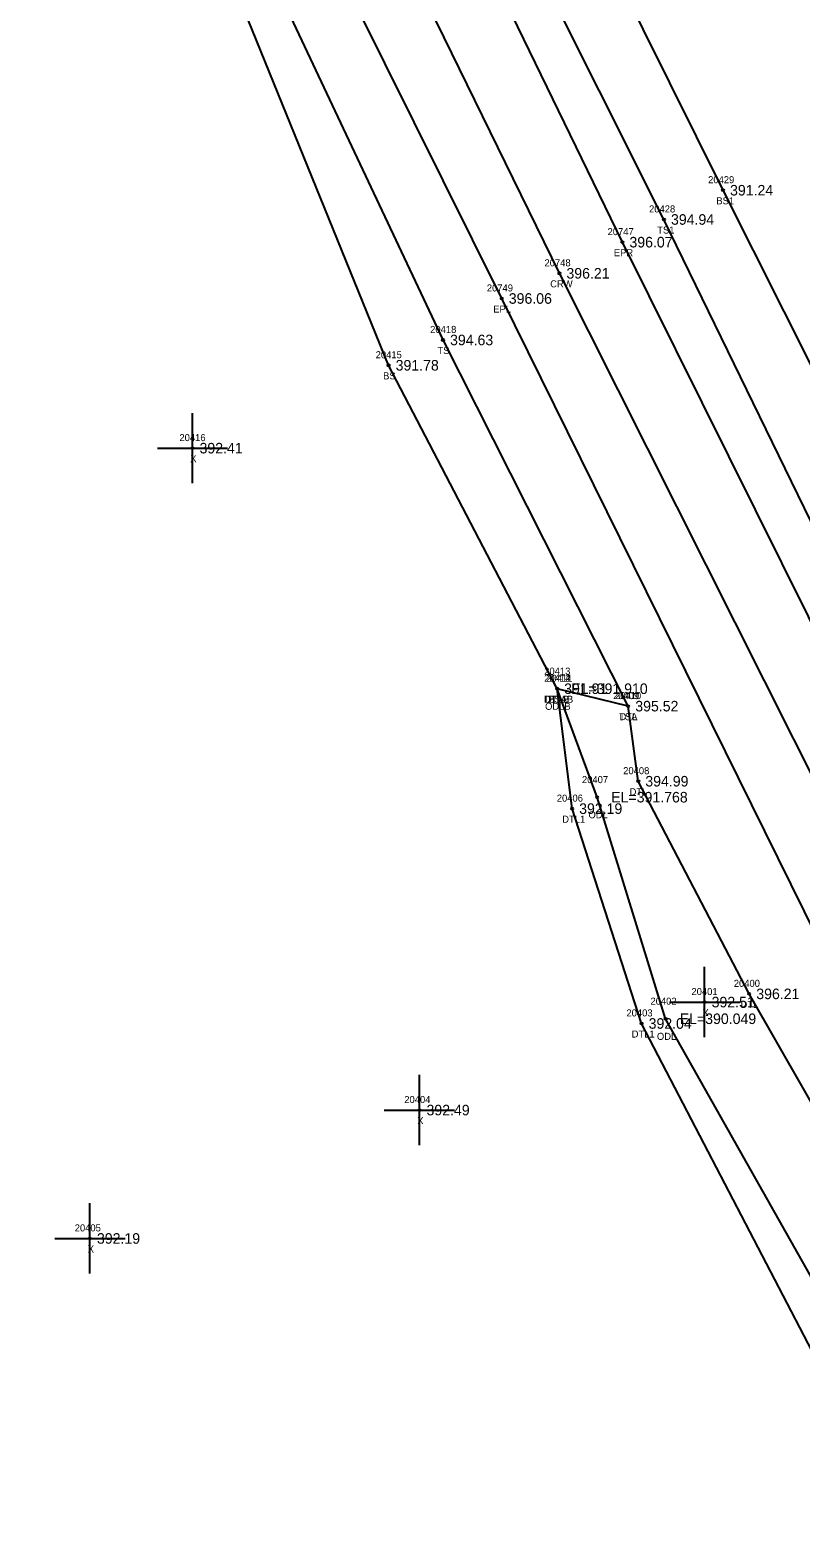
# Model space of a CAD drawing. Extents: x 2186623 to 2187804, y 1079975 to 1082766.
# Drawn here: x 2187266 to 2187375.6, y 1081383.3 to 1081597.8 of the extents above; entities that cross this region are included whole.
import ezdxf

# ---------------------------------------------------------------- set-up
doc = ezdxf.new("R2010")
doc.units = 0
for name, color, linetype in [('RD_DTM_BkLn1', 7, 'Continuous'), ('RD_DTM_BkLn2', 7, 'Continuous'), ('RD_DTM_BkLn_txCode', 7, 'Continuous'), ('RD_EX_H2O', 7, 'Continuous'), ('RD_EX_H2O_txCode', 7, 'Continuous'), ('RD_EX_Misc', 7, 'Continuous'), ('RD_EX_Misc_txCode', 7, 'Continuous'), ('RD_EX_Road', 7, 'Continuous'), ('RD_EX_Road_txCode', 7, 'Continuous'), ('RD_EX_TX_H2O_ELEV', 7, 'Continuous'), ('RD_EX_TX_Misc_ELEV', 7, 'Continuous'), ('RD_EX_TX_Road_ELEV', 7, 'Continuous'), ('RD_HC_Survey_ELEV', 7, 'Continuous'), ('RD_HC_Survey_txCode', 7, 'Continuous'), ('RD_SMD_Locator', 7, 'Continuous')]:
    doc.layers.add(name, color=color, linetype=linetype)

msp = doc.modelspace()

# ---------------------------------------------------------------- linework, layer by layer
at = {"layer": 'RD_DTM_BkLn1'}
msp.add_lwpolyline([(2187423.87, 1081398.18), (2187387.08, 1081472.03), (2187341.23, 1081563.21), (2187295.24, 1081657.28), (2187251.34, 1081744.68), (2187208.12, 1081834.1), (2187164.51, 1081922.08), (2187120.25, 1082011.57), (2187076.78, 1082099.89), (2187032.8, 1082188.99), (2186987.81, 1082278.27), (2186943.85, 1082367.59), (2186899.96, 1082456.58), (2186856.34, 1082544.86), (2186810.78, 1082636.89), (2186773.78, 1082711.06)], dxfattribs=at)
at = {"layer": 'RD_DTM_BkLn2'}
for points in [[(2187383.36, 1081514.91), (2187356.1, 1081570.87), (2187310.01, 1081662.87), (2187268.1, 1081753.93), (2187240.79, 1081807.4)], [(2187390.49, 1081523.34), (2187364.5, 1081575.03), (2187318.98, 1081666.8), (2187274.04, 1081756.37), (2187249.06, 1081806.96)], [(2187351.02, 1081501.64), (2187324.68, 1081553.73), (2187280.23, 1081648.12), (2187237.66, 1081737.12), (2187231.79, 1081749.81)], [(2187340.91, 1081504.12), (2187316.94, 1081550.13), (2187277.62, 1081646.94), (2187235.56, 1081736.09), (2187229.68, 1081747.29)]]:
    msp.add_lwpolyline(points, dxfattribs=at)
at = {"layer": 'RD_EX_H2O'}
for points in [[(2187397.97, 1081383.33), (2187356.34, 1081457.17), (2187346.6, 1081488.69), (2187340.91, 1081504.12)], [(2187390.81, 1081383.67), (2187352.92, 1081456.5), (2187343.04, 1081487.06), (2187340.91, 1081504.12)], [(2187407.94, 1081391.28), (2187368.23, 1081460.71), (2187352.45, 1081490.96), (2187351.02, 1081501.64), (2187340.91, 1081504.12)]]:
    msp.add_lwpolyline(points, dxfattribs=at)
at = {"layer": 'RD_EX_Misc'}
for p, q in [((2187289.05, 1081533.34), (2187289.05, 1081543.34)), ((2187284.05, 1081538.34), (2187294.05, 1081538.34)), ((2187361.88, 1081454.54), (2187361.88, 1081464.54)), ((2187356.88, 1081459.54), (2187366.88, 1081459.54)), ((2187321.33, 1081439.18), (2187321.33, 1081449.18)), ((2187316.33, 1081444.18), (2187326.33, 1081444.18)), ((2187274.46, 1081420.92), (2187274.46, 1081430.92)), ((2187269.46, 1081425.92), (2187279.46, 1081425.92))]:
    msp.add_line(p, q, dxfattribs=at)
at = {"layer": 'RD_EX_Road'}
for points in [[(2187433.48, 1081402.93), (2187431.23, 1081405.14), (2187428.77, 1081409.96), (2187395.59, 1081476.3), (2187350.19, 1081567.64), (2187304.81, 1081661.14), (2187260.59, 1081749.11), (2187216.69, 1081837.7), (2187187.21, 1081897.62), (2187180.39, 1081911.5), (2187172.85, 1081926.68), (2187129.14, 1082015.5), (2187085.24, 1082104.53), (2187041.33, 1082193.41), (2186996.73, 1082282.37), (2186965.72, 1082345.62), (2186953.24, 1082372.4), (2186921.8, 1082435.38), (2186908.96, 1082460.32), (2186865.29, 1082548.82), (2186820.07, 1082641.92), (2186783.9, 1082716)], [(2187412.76, 1081392.41), (2187413.27, 1081397.3), (2187377.92, 1081468.69), (2187333.03, 1081559.63), (2187287.24, 1081651.83), (2187243.42, 1081739.85), (2187221.49, 1081785.01), (2187215.17, 1081798.71), (2187200.07, 1081829.29), (2187156, 1081917.87), (2187111.96, 1082007.49), (2187067.92, 1082095.45), (2187048.95, 1082133.44), (2187040.02, 1082149.93), (2187023.25, 1082184.23), (2186978.93, 1082274.21), (2186935.28, 1082363.16), (2186891.66, 1082452.64), (2186848.32, 1082541.12), (2186802.48, 1082632.77), (2186765.18, 1082707.62)]]:
    msp.add_lwpolyline(points, dxfattribs=at)
at = {"layer": 'RD_SMD_Locator'}
for centre in [(2187364.5, 1081575.03), (2187356.1, 1081570.87), (2187350.19, 1081567.64), (2187341.23, 1081563.21), (2187333.03, 1081559.63), (2187324.68, 1081553.73), (2187316.94, 1081550.13), (2187289.05, 1081538.34), (2187340.91, 1081504.12), (2187340.91, 1081504.12), (2187340.91, 1081504.12), (2187340.91, 1081504.12), (2187351.02, 1081501.64), (2187351.02, 1081501.64), (2187352.45, 1081490.96), (2187346.6, 1081488.69), (2187343.04, 1081487.06), (2187368.23, 1081460.71), (2187361.88, 1081459.54), (2187352.92, 1081456.5), (2187356.34, 1081457.17), (2187321.33, 1081444.18), (2187274.46, 1081425.92)]:
    msp.add_circle(centre, 0.15, dxfattribs=at)

# ---------------------------------------------------------------- texts
at = {"layer": 'RD_DTM_BkLn_txCode'}
for s, p in [('20429', (2187362.38, 1081576.03)), ('20428', (2187353.98, 1081571.87)), ('BS1', (2187363.55, 1081573.03)), ('TS1', (2187355.14, 1081568.87)), ('20418', (2187322.85, 1081554.73)), ('TS', (2187323.88, 1081551.73)), ('20415', (2187315.1, 1081551.13)), ('BS', (2187316.16, 1081548.13)), ('20414', (2187339.07, 1081505.12)), ('20410', (2187349.14, 1081502.64)), ('BSA', (2187339.64, 1081502.12)), ('TSA', (2187349.73, 1081499.64))]:
    msp.add_text(s, height=1, dxfattribs=at).set_placement(p)
at = {"layer": 'RD_EX_H2O_txCode'}
for s, p in [('20413', (2187339.07, 1081506.12)), ('20412', (2187339.07, 1081505.12)), ('20411', (2187339.36, 1081505.12)), ('20409', (2187348.86, 1081502.64)), ('DTL1B', (2187339.03, 1081502.12)), ('ODLB', (2187339.19, 1081501.12)), ('DTLB', (2187339.19, 1081502.12)), ('DTL', (2187349.77, 1081499.64)), ('20408', (2187350.3, 1081491.96)), ('20407', (2187344.44, 1081490.69)), ('20406', (2187340.86, 1081488.06)), ('DTL', (2187351.21, 1081488.96)), ('ODL', (2187345.36, 1081485.69)), ('DTL1', (2187341.63, 1081485.06)), ('20400', (2187366.03, 1081461.71)), ('20403', (2187350.76, 1081457.5)), ('20402', (2187354.18, 1081459.17)), ('DTL', (2187366.99, 1081458.71)), ('DTL1', (2187351.51, 1081454.5)), ('ODL', (2187355.1, 1081454.17))]:
    msp.add_text(s, height=1, dxfattribs=at).set_placement(p)
at = {"layer": 'RD_EX_Misc_txCode'}
for s, p in [('20416', (2187287.19, 1081539.34)), ('X', (2187288.73, 1081536.34)), ('20401', (2187360.01, 1081460.54)), ('X', (2187361.57, 1081457.54)), ('20404', (2187319.17, 1081445.18)), ('X', (2187321.01, 1081442.18)), ('20405', (2187272.3, 1081426.92)), ('X', (2187274.15, 1081423.92))]:
    msp.add_text(s, height=1, dxfattribs=at).set_placement(p)
at = {"layer": 'RD_EX_Road_txCode'}
for s, p in [('20747', (2187348.08, 1081568.64)), ('EPR', (2187348.97, 1081565.64)), ('20749', (2187330.91, 1081560.63)), ('EPL', (2187331.82, 1081557.63))]:
    msp.add_text(s, height=1, dxfattribs=at).set_placement(p)
at = {"layer": 'RD_EX_TX_H2O_ELEV'}
for s, p in [('391.91', (2187341.91, 1081503.37)), ('391.91', (2187341.91, 1081503.37)), ('EL=391.910', (2187342.91, 1081503.37)), ('395.52', (2187352.02, 1081500.89)), ('394.99', (2187353.45, 1081490.21)), ('EL=391.768', (2187348.6, 1081487.94)), ('392.19', (2187344.04, 1081486.31)), ('396.21', (2187369.23, 1081459.96)), ('392.04', (2187353.92, 1081455.75)), ('EL=390.049', (2187358.34, 1081456.42))]:
    msp.add_text(s, height=1.5, dxfattribs=at).set_placement(p)
at = {"layer": 'RD_EX_TX_Misc_ELEV'}
for s, p in [('391.24', (2187365.5, 1081574.28)), ('394.94', (2187357.1, 1081570.12)), ('394.63', (2187325.68, 1081552.98)), ('391.78', (2187317.94, 1081549.38)), ('392.41', (2187290.05, 1081537.59)), ('391.91', (2187341.91, 1081503.37)), ('395.52', (2187352.02, 1081500.89)), ('392.51', (2187362.88, 1081458.79)), ('392.49', (2187322.33, 1081443.43)), ('392.19', (2187275.46, 1081425.17))]:
    msp.add_text(s, height=1.5, dxfattribs=at).set_placement(p)
at = {"layer": 'RD_EX_TX_Road_ELEV'}
for s, p in [('396.07', (2187351.19, 1081566.89)), ('396.06', (2187334.03, 1081558.88))]:
    msp.add_text(s, height=1.5, dxfattribs=at).set_placement(p)
at = {"layer": 'RD_HC_Survey_ELEV'}
msp.add_text('396.21', height=1.5, dxfattribs=at).set_placement((2187342.23, 1081562.46))
at = {"layer": 'RD_HC_Survey_txCode'}
for s, p in [('20748', (2187339.11, 1081564.21)), ('CRW', (2187339.92, 1081561.21))]:
    msp.add_text(s, height=1, dxfattribs=at).set_placement(p)

doc.saveas('drawing.dxf')
